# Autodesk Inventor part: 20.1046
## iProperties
Created: 2013-02
Part Number: 20.1046
Material: Aluminum-6061
Description: PROFILE 45X45 R
Document SubType Name: Modeling
Designer: Administrator
Density: 2.71 g/cm^3
FINISH: CLEAR ANODIZED
Author: Administrator
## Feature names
1. Extrusion1
2. Extrusion2
3. Mirror1
4. OVERTRAVEL MARK [Extrusion]
5. Mirror2
